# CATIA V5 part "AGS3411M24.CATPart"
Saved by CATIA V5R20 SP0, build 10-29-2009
Part number: AGS3411M24
Definition: NONE
Nomenclature: AGS3411M24
Source: Unknown
Description: AGS3411M24
Bounding box of the stored display mesh (mm): x -35 to 33, y -17.347 to 17.347, z -14 to 14
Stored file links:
  C:\Users\Utente\Desktop\IO LAVORO\3D X SITO CF\X SITO\PLASTICA\AGS\AGS3411M24.CATPart
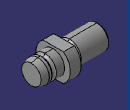
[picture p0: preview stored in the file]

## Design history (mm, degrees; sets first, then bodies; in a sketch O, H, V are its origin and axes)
Body1 "AGS3411M24" (main body)
  Solid1: solid without history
